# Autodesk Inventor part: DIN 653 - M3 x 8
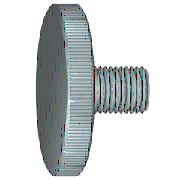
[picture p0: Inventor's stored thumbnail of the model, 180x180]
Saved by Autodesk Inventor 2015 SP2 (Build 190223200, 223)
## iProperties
Created: 2012-02
Part Number: DIN 653 - M3 x 8
Material: Stahl, weich
Description: Rändelschraube
Document SubType Name: Modeling
Standard: DIN 653
Designer: rYan
Standards Organization: DIN
Language: de-DE
Size Designation: M3 x 8
Categories: <MemberInstance><Categories><Category DisplayName="Verbindungselemente" InternalName="e4da775c-781d-43d5-af7c-5136215cf5a6" Mnemonic="FSTN"><Category DisplayNam
Density: 7.85 g/cm^3
Appearance: Halbpoliert
IsCustomPart: 0
Author: rYan
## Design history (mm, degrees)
revolve "Körper" stored, may be unused: angle "d8" = 90 deg
node "IDS_WORKPLANE{1}"
workplane "Work Plane2"
body "Solid1"
feature "Gewinde" dims "d2" = 6.224 (= GEL - 0.092 x GD), "d3" = 0
chamfer "Fase1" distance "d10" = 0.3 (= PHH); stored, may be unused: angle "d11" = 45 deg (= FAWI), second distance "d38" = 0.3 (= PHH)
sketch "Skizze1"
  geometry: L1 (-2.5, 0)-(8, 0); L2 (8, 0)-(8, 5); L3 (7.673, 1.5)-(0, 1.5); L4 (0, -1.2)-(0, 7.2) reference; L5 (0, 1.5)-(0, 6); L6 (0, 6)-(-2.5, 6); L7 (-2.5, 6)-(-2.5, 0); L8 (-4.616, 0)-(10.197, 0) reference; A1 r 3.6 centre (4.4, 0) between (8, 0) and (7.673, 1.5)
  constraints: 13 end point, 2 perpendicular, 2 point on circle, 2 vertical alignment, 1 centre point, 1 collinear, 1 parallel, 1 point on line, 1 tangent
  dimensions: "d1" = 3 diameter of L3 L1 (= GD); "d6" = 12 diameter of L6 L1 (= KOD); "d7" = 2.5 distance between parallel lines of L5 L7 (= KOH); "d9" = 3.6 radius of A1 (= 1.2 x GD); "d41" = 8 distance between parallel lines of L2 L5 (= NLG)
other parameters: "GD" = 3 [user parameter; used in 3 equation terms], "NLG" = 8 [user parameter; used in 1 equation term], "GEL" = 6.5 [user parameter; used in 1 equation term], "KOD" = 12 [user parameter; used in 1 equation term], "KOH" = 2.5 [user parameter; used in 2 equation terms], "GAL" = 0.30673 (= 0.61345 x PTC) [user parameter], "d4" = 0, "SD" = 0 [user parameter], "LADI" = 3 (= NND) [user parameter], "PHH" = 0.3 [user parameter; used in 2 equation terms], "FAWI" = 45 deg [user parameter; used in 1 equation term], "d12" = -1.25 (= -0.5 x KOH), "T" = 0.5 [user parameter], "d39" = 0, "d42" = 0, "NND" = 3 [user parameter; used in 1 equation term], "PTC" = 0.5 [user parameter; used in 2 equation terms]
